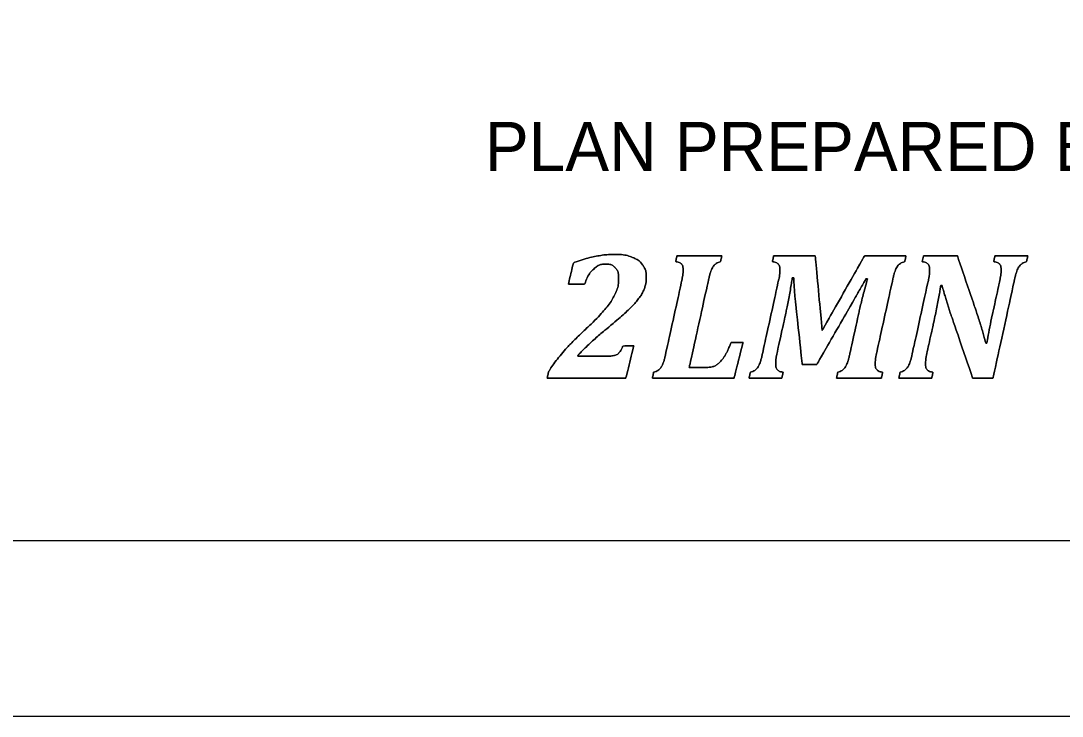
# Model space of a CAD drawing. Extents: x 0 to 36.9, y 0 to 22.
# Drawn here: x 2.291 to 5.257, y 0 to 1.981 of the extents above; entities that cross this region are included whole.
import ezdxf

# ---------------------------------------------------------------- set-up
doc = ezdxf.new("R2010")
doc.units = 0
for name, color, linetype in [('SH_Border', 7, 'Continuous'), ('SH_Cut_Line', 7, 'Continuous'), ('SH_Data', 7, 'Continuous'), ('SH_Text', 7, 'Continuous')]:
    doc.layers.add(name, color=color, linetype=linetype)

msp = doc.modelspace()

# ---------------------------------------------------------------- linework, layer by layer
at = {"layer": 'SH_Border'}
msp.add_lwpolyline([(1.5, 21.5), (33.5, 21.5), (33.5, 0.5), (1.5, 0.5)], close=True, dxfattribs=at)
at = {"layer": 'SH_Cut_Line'}
msp.add_lwpolyline([(0, 0), (34, 0), (34, 22), (0, 22)], close=True, dxfattribs=at)
at = {"layer": 'SH_Data'}
for points in [[(3.9615, 1.026), (3.9703, 1.026), (3.9771, 1.0266), (3.982, 1.0279), (3.9868, 1.0292), (3.9909, 1.0315), (3.9943, 1.035), (3.9977, 1.0385), (4.0014, 1.0451), (4.0055, 1.0548), (4.0055, 1.0548), (4.0365, 1.0548), (4.0365, 1.0548), (4.0365, 1.0548), (4.0139, 0.9635), (4.0139, 0.9635), (4.0139, 0.9635), (3.79, 0.9635), (3.79, 0.9635), (3.79, 0.9635), (3.7936, 0.9803), (3.7936, 0.9803), (3.8025, 0.9958), (3.8148, 1.0128), (3.8304, 1.0313), (3.846, 1.0499), (3.8678, 1.0725), (3.896, 1.0992), (3.9217, 1.1235), (3.9411, 1.1434), (3.954, 1.1588), (3.967, 1.1742), (3.9768, 1.189), (3.9835, 1.2033), (3.9902, 1.2176), (3.9935, 1.2324), (3.9935, 1.2477), (3.9935, 1.2601), (3.9903, 1.2699), (3.9839, 1.2771), (3.9774, 1.2844), (3.9688, 1.288), (3.958, 1.288), (3.9442, 1.288), (3.9324, 1.2833), (3.9224, 1.274), (3.9124, 1.2646), (3.9038, 1.2502), (3.8965, 1.2308), (3.8965, 1.2308), (3.8502, 1.2308), (3.8502, 1.2308), (3.8502, 1.2308), (3.8647, 1.2921), (3.8647, 1.2921), (3.8903, 1.3009), (3.9118, 1.307), (3.9294, 1.3104), (3.9469, 1.3138), (3.9645, 1.3155), (3.9821, 1.3155), (4.0024, 1.3155), (4.0194, 1.3127), (4.033, 1.307), (4.0467, 1.3013), (4.0566, 1.2936), (4.0629, 1.2839), (4.0692, 1.2742), (4.0723, 1.2632), (4.0723, 1.251), (4.0723, 1.2396), (4.0704, 1.2288), (4.0667, 1.2187), (4.063, 1.2086), (4.0568, 1.1981), (4.0483, 1.1871), (4.0397, 1.1761), (4.0281, 1.1639), (4.0135, 1.1503), (3.9988, 1.1368), (3.9784, 1.1193), (3.9521, 1.0977), (3.9397, 1.0875), (3.9264, 1.0757), (3.9121, 1.0625), (3.8978, 1.0492), (3.8864, 1.0379), (3.8779, 1.0285), (3.8779, 1.0285), (3.8774, 1.026), (3.8774, 1.026), (3.8774, 1.026), (3.9615, 1.026), (3.9615, 1.026)], [(3.9615, 1.026), (3.9615, 1.026), (3.8774, 1.026), (3.8774, 1.026), (3.8774, 1.026), (3.8779, 1.0285), (3.8779, 1.0285), (3.8864, 1.0379), (3.8978, 1.0492), (3.9121, 1.0625), (3.9264, 1.0757), (3.9397, 1.0875), (3.9521, 1.0977), (3.9784, 1.1193), (3.9988, 1.1368), (4.0135, 1.1503), (4.0281, 1.1639), (4.0397, 1.1761), (4.0483, 1.1871), (4.0568, 1.1981), (4.063, 1.2086), (4.0667, 1.2187), (4.0704, 1.2288), (4.0723, 1.2396), (4.0723, 1.251), (4.0723, 1.2632), (4.0692, 1.2742), (4.0629, 1.2839), (4.0566, 1.2936), (4.0467, 1.3013), (4.033, 1.307), (4.0194, 1.3127), (4.0024, 1.3155), (3.9821, 1.3155), (3.9645, 1.3155), (3.9469, 1.3138), (3.9294, 1.3104), (3.9118, 1.307), (3.8903, 1.3009), (3.8647, 1.2921), (3.8647, 1.2921), (3.8502, 1.2308), (3.8502, 1.2308), (3.8502, 1.2308), (3.8965, 1.2308), (3.8965, 1.2308), (3.9038, 1.2502), (3.9124, 1.2646), (3.9224, 1.274), (3.9324, 1.2833), (3.9442, 1.288), (3.958, 1.288), (3.9688, 1.288), (3.9774, 1.2844), (3.9839, 1.2771), (3.9903, 1.2699), (3.9935, 1.2601), (3.9935, 1.2477), (3.9935, 1.2324), (3.9902, 1.2176), (3.9835, 1.2033), (3.9768, 1.189), (3.967, 1.1742), (3.954, 1.1588), (3.9411, 1.1434), (3.9217, 1.1235), (3.896, 1.0992), (3.8678, 1.0725), (3.846, 1.0499), (3.8304, 1.0313), (3.8148, 1.0128), (3.8025, 0.9958), (3.7936, 0.9803), (3.7936, 0.9803), (3.79, 0.9635), (3.79, 0.9635), (3.79, 0.9635), (4.0139, 0.9635), (4.0139, 0.9635), (4.0139, 0.9635), (4.0365, 1.0548), (4.0365, 1.0548), (4.0365, 1.0548), (4.0055, 1.0548), (4.0055, 1.0548), (4.0014, 1.0451), (3.9977, 1.0385), (3.9943, 1.035), (3.9909, 1.0315), (3.9868, 1.0292), (3.982, 1.0279), (3.9771, 1.0266), (3.9703, 1.026), (3.9615, 1.026)], [(4.2425, 0.9938), (4.2508, 0.9938), (4.2573, 0.9945), (4.2618, 0.9959), (4.2664, 0.9972), (4.2706, 0.9994), (4.2743, 1.0022), (4.278, 1.0051), (4.2821, 1.0091), (4.2866, 1.0142), (4.2911, 1.0193), (4.2955, 1.026), (4.3, 1.0341), (4.3044, 1.0423), (4.3088, 1.0525), (4.3134, 1.0648), (4.3134, 1.0648), (4.348, 1.0648), (4.348, 1.0648), (4.348, 1.0648), (4.3221, 0.9635), (4.3221, 0.9635), (4.3221, 0.9635), (4.0896, 0.9635), (4.0896, 0.9635), (4.0896, 0.9635), (4.0931, 0.9803), (4.0931, 0.9803), (4.1002, 0.9823), (4.1057, 0.9852), (4.1095, 0.9887), (4.1133, 0.9923), (4.1166, 0.9974), (4.1193, 1.0039), (4.122, 1.0104), (4.1247, 1.0199), (4.1274, 1.0324), (4.1274, 1.0324), (4.1737, 1.2428), (4.1737, 1.2428), (4.1759, 1.2529), (4.177, 1.2628), (4.177, 1.2727), (4.177, 1.2798), (4.1753, 1.2851), (4.172, 1.2884), (4.1687, 1.2917), (4.1633, 1.2939), (4.1559, 1.2949), (4.1559, 1.2949), (4.1594, 1.3117), (4.1594, 1.3117), (4.1594, 1.3117), (4.2872, 1.3117), (4.2872, 1.3117), (4.2872, 1.3117), (4.2837, 1.2949), (4.2837, 1.2949), (4.2766, 1.2928), (4.2711, 1.29), (4.2673, 1.2865), (4.2635, 1.2829), (4.2602, 1.2778), (4.2575, 1.2713), (4.2548, 1.2647), (4.2521, 1.2552), (4.2494, 1.2428), (4.2494, 1.2428), (4.1945, 0.9938), (4.1945, 0.9938), (4.1945, 0.9938), (4.2425, 0.9938), (4.2425, 0.9938)], [(4.2425, 0.9938), (4.2425, 0.9938), (4.1945, 0.9938), (4.1945, 0.9938), (4.1945, 0.9938), (4.2494, 1.2428), (4.2494, 1.2428), (4.2521, 1.2552), (4.2548, 1.2647), (4.2575, 1.2713), (4.2602, 1.2778), (4.2635, 1.2829), (4.2673, 1.2865), (4.2711, 1.29), (4.2766, 1.2928), (4.2837, 1.2949), (4.2837, 1.2949), (4.2872, 1.3117), (4.2872, 1.3117), (4.2872, 1.3117), (4.1594, 1.3117), (4.1594, 1.3117), (4.1594, 1.3117), (4.1559, 1.2949), (4.1559, 1.2949), (4.1633, 1.2939), (4.1687, 1.2917), (4.172, 1.2884), (4.1753, 1.2851), (4.177, 1.2798), (4.177, 1.2727), (4.177, 1.2628), (4.1759, 1.2529), (4.1737, 1.2428), (4.1737, 1.2428), (4.1274, 1.0324), (4.1274, 1.0324), (4.1247, 1.0199), (4.122, 1.0104), (4.1193, 1.0039), (4.1166, 0.9974), (4.1133, 0.9923), (4.1095, 0.9887), (4.1057, 0.9852), (4.1002, 0.9823), (4.0931, 0.9803), (4.0931, 0.9803), (4.0896, 0.9635), (4.0896, 0.9635), (4.0896, 0.9635), (4.3221, 0.9635), (4.3221, 0.9635), (4.3221, 0.9635), (4.348, 1.0648), (4.348, 1.0648), (4.348, 1.0648), (4.3134, 1.0648), (4.3134, 1.0648), (4.3088, 1.0525), (4.3044, 1.0423), (4.3, 1.0341), (4.2955, 1.026), (4.2911, 1.0193), (4.2866, 1.0142), (4.2821, 1.0091), (4.278, 1.0051), (4.2743, 1.0022), (4.2706, 0.9994), (4.2664, 0.9972), (4.2618, 0.9959), (4.2573, 0.9945), (4.2508, 0.9938), (4.2425, 0.9938)], [(4.5533, 1.3117), (4.5533, 1.3117), (4.5731, 1.0987), (4.5731, 1.0987), (4.5731, 1.0987), (4.6935, 1.3117), (4.6935, 1.3117), (4.6935, 1.3117), (4.8117, 1.3117), (4.8117, 1.3117), (4.8117, 1.3117), (4.8081, 1.2949), (4.8081, 1.2949), (4.801, 1.2928), (4.7955, 1.29), (4.7917, 1.2865), (4.7879, 1.2829), (4.7846, 1.2778), (4.7819, 1.2713), (4.7792, 1.2647), (4.7765, 1.2552), (4.7738, 1.2428), (4.7738, 1.2428), (4.7276, 1.0324), (4.7276, 1.0324), (4.7265, 1.0279), (4.7259, 1.0244), (4.7255, 1.0219), (4.7252, 1.0193), (4.7249, 1.0166), (4.7246, 1.0136), (4.7244, 1.0106), (4.7243, 1.0069), (4.7243, 1.0025), (4.7243, 0.9954), (4.7259, 0.9901), (4.7292, 0.9868), (4.7325, 0.9835), (4.7379, 0.9813), (4.7453, 0.9803), (4.7453, 0.9803), (4.7418, 0.9635), (4.7418, 0.9635), (4.7418, 0.9635), (4.614, 0.9635), (4.614, 0.9635), (4.614, 0.9635), (4.6175, 0.9803), (4.6175, 0.9803), (4.6247, 0.9823), (4.6301, 0.9852), (4.6339, 0.9887), (4.6377, 0.9923), (4.641, 0.9974), (4.6437, 1.0039), (4.6464, 1.0104), (4.6491, 1.0199), (4.6518, 1.0324), (4.6518, 1.0324), (4.6752, 1.1395), (4.6752, 1.1395), (4.6778, 1.1511), (4.6814, 1.1665), (4.6861, 1.1858), (4.6909, 1.2051), (4.6964, 1.2253), (4.7027, 1.2464), (4.7027, 1.2464), (4.6976, 1.2464), (4.6976, 1.2464), (4.6896, 1.2318), (4.6811, 1.2165), (4.6719, 1.2007), (4.6719, 1.2007), (4.5576, 1.002), (4.5576, 1.002), (4.5576, 1.002), (4.5164, 1.002), (4.5164, 1.002), (4.5164, 1.002), (4.4997, 1.1553), (4.4997, 1.1553), (4.4975, 1.1747), (4.4958, 1.1916), (4.4947, 1.2061), (4.4936, 1.2205), (4.4927, 1.2348), (4.492, 1.249), (4.492, 1.249), (4.488, 1.249), (4.488, 1.249), (4.4856, 1.2333), (4.4825, 1.2154), (4.4788, 1.1952), (4.4751, 1.1751), (4.4717, 1.1581), (4.4687, 1.1444), (4.4687, 1.1444), (4.444, 1.0324), (4.444, 1.0324), (4.443, 1.0279), (4.4423, 1.0244), (4.442, 1.0219), (4.4416, 1.0193), (4.4413, 1.0166), (4.4411, 1.0136), (4.4408, 1.0106), (4.4407, 1.0069), (4.4407, 1.0025), (4.4407, 0.9954), (4.4424, 0.9901), (4.4457, 0.9868), (4.449, 0.9835), (4.4543, 0.9813), (4.4618, 0.9803), (4.4618, 0.9803), (4.4582, 0.9635), (4.4582, 0.9635), (4.4582, 0.9635), (4.365, 0.9635), (4.365, 0.9635), (4.365, 0.9635), (4.3686, 0.9803), (4.3686, 0.9803), (4.3757, 0.9823), (4.3811, 0.9852), (4.3849, 0.9887), (4.3888, 0.9923), (4.392, 0.9974), (4.3947, 1.0039), (4.3974, 1.0104), (4.4001, 1.0199), (4.4029, 1.0324), (4.4029, 1.0324), (4.4491, 1.2428), (4.4491, 1.2428), (4.4513, 1.2529), (4.4524, 1.2628), (4.4524, 1.2727), (4.4524, 1.2798), (4.4507, 1.2851), (4.4474, 1.2884), (4.4441, 1.2917), (4.4388, 1.2939), (4.4313, 1.2949), (4.4313, 1.2949), (4.4349, 1.3117), (4.4349, 1.3117), (4.4349, 1.3117), (4.5533, 1.3117), (4.5533, 1.3117)], [(4.5533, 1.3117), (4.5533, 1.3117), (4.4349, 1.3117), (4.4349, 1.3117), (4.4349, 1.3117), (4.4313, 1.2949), (4.4313, 1.2949), (4.4388, 1.2939), (4.4441, 1.2917), (4.4474, 1.2884), (4.4507, 1.2851), (4.4524, 1.2798), (4.4524, 1.2727), (4.4524, 1.2628), (4.4513, 1.2529), (4.4491, 1.2428), (4.4491, 1.2428), (4.4029, 1.0324), (4.4029, 1.0324), (4.4001, 1.0199), (4.3974, 1.0104), (4.3947, 1.0039), (4.392, 0.9974), (4.3888, 0.9923), (4.3849, 0.9887), (4.3811, 0.9852), (4.3757, 0.9823), (4.3686, 0.9803), (4.3686, 0.9803), (4.365, 0.9635), (4.365, 0.9635), (4.365, 0.9635), (4.4582, 0.9635), (4.4582, 0.9635), (4.4582, 0.9635), (4.4618, 0.9803), (4.4618, 0.9803), (4.4543, 0.9813), (4.449, 0.9835), (4.4457, 0.9868), (4.4424, 0.9901), (4.4407, 0.9954), (4.4407, 1.0025), (4.4407, 1.0069), (4.4408, 1.0106), (4.4411, 1.0136), (4.4413, 1.0166), (4.4416, 1.0193), (4.442, 1.0219), (4.4423, 1.0244), (4.443, 1.0279), (4.444, 1.0324), (4.444, 1.0324), (4.4687, 1.1444), (4.4687, 1.1444), (4.4717, 1.1581), (4.4751, 1.1751), (4.4788, 1.1952), (4.4825, 1.2154), (4.4856, 1.2333), (4.488, 1.249), (4.488, 1.249), (4.492, 1.249), (4.492, 1.249), (4.4927, 1.2348), (4.4936, 1.2205), (4.4947, 1.2061), (4.4958, 1.1916), (4.4975, 1.1747), (4.4997, 1.1553), (4.4997, 1.1553), (4.5164, 1.002), (4.5164, 1.002), (4.5164, 1.002), (4.5576, 1.002), (4.5576, 1.002), (4.5576, 1.002), (4.6719, 1.2007), (4.6719, 1.2007), (4.6811, 1.2165), (4.6896, 1.2318), (4.6976, 1.2464), (4.6976, 1.2464), (4.7027, 1.2464), (4.7027, 1.2464), (4.6964, 1.2253), (4.6909, 1.2051), (4.6861, 1.1858), (4.6814, 1.1665), (4.6778, 1.1511), (4.6752, 1.1395), (4.6752, 1.1395), (4.6518, 1.0324), (4.6518, 1.0324), (4.6491, 1.0199), (4.6464, 1.0104), (4.6437, 1.0039), (4.641, 0.9974), (4.6377, 0.9923), (4.6339, 0.9887), (4.6301, 0.9852), (4.6247, 0.9823), (4.6175, 0.9803), (4.6175, 0.9803), (4.614, 0.9635), (4.614, 0.9635), (4.614, 0.9635), (4.7418, 0.9635), (4.7418, 0.9635), (4.7418, 0.9635), (4.7453, 0.9803), (4.7453, 0.9803), (4.7379, 0.9813), (4.7325, 0.9835), (4.7292, 0.9868), (4.7259, 0.9901), (4.7243, 0.9954), (4.7243, 1.0025), (4.7243, 1.0069), (4.7244, 1.0106), (4.7246, 1.0136), (4.7249, 1.0166), (4.7252, 1.0193), (4.7255, 1.0219), (4.7259, 1.0244), (4.7265, 1.0279), (4.7276, 1.0324), (4.7276, 1.0324), (4.7738, 1.2428), (4.7738, 1.2428), (4.7765, 1.2552), (4.7792, 1.2647), (4.7819, 1.2713), (4.7846, 1.2778), (4.7879, 1.2829), (4.7917, 1.2865), (4.7955, 1.29), (4.801, 1.2928), (4.8081, 1.2949), (4.8081, 1.2949), (4.8117, 1.3117), (4.8117, 1.3117), (4.8117, 1.3117), (4.6935, 1.3117), (4.6935, 1.3117), (4.6935, 1.3117), (4.5731, 1.0987), (4.5731, 1.0987), (4.5731, 1.0987), (4.5533, 1.3117), (4.5533, 1.3117)], [(4.8615, 1.3117), (4.8615, 1.3117), (4.958, 1.3117), (4.958, 1.3117), (4.958, 1.3117), (5.007, 1.1673), (5.007, 1.1673), (5.0204, 1.128), (5.031, 1.0933), (5.0388, 1.0632), (5.0388, 1.0632), (5.0421, 1.0632), (5.0421, 1.0632), (5.047, 1.0926), (5.0535, 1.1252), (5.0614, 1.1609), (5.0614, 1.1609), (5.0792, 1.2428), (5.0792, 1.2428), (5.0814, 1.253), (5.0825, 1.263), (5.0825, 1.2727), (5.0825, 1.2798), (5.0809, 1.2851), (5.0776, 1.2884), (5.0743, 1.2917), (5.0689, 1.2939), (5.0614, 1.2949), (5.0614, 1.2949), (5.065, 1.3117), (5.065, 1.3117), (5.065, 1.3117), (5.1585, 1.3117), (5.1585, 1.3117), (5.1585, 1.3117), (5.1549, 1.2949), (5.1549, 1.2949), (5.1478, 1.2928), (5.1423, 1.29), (5.1385, 1.2865), (5.1347, 1.2829), (5.1315, 1.2778), (5.1288, 1.2713), (5.126, 1.2647), (5.1233, 1.2552), (5.1206, 1.2428), (5.1206, 1.2428), (5.0594, 0.9635), (5.0594, 0.9635), (5.0594, 0.9635), (5.0015, 0.9635), (5.0015, 0.9635), (5.0015, 0.9635), (4.9405, 1.1418), (4.9405, 1.1418), (4.9357, 1.1557), (4.9315, 1.1688), (4.9278, 1.181), (4.924, 1.1931), (4.9196, 1.2086), (4.9143, 1.2273), (4.9143, 1.2273), (4.9105, 1.2275), (4.9105, 1.2275), (4.9091, 1.2161), (4.9066, 1.2004), (4.9027, 1.1805), (4.8989, 1.1605), (4.8944, 1.1388), (4.8892, 1.1155), (4.8892, 1.1155), (4.8709, 1.0324), (4.8709, 1.0324), (4.8698, 1.0279), (4.8692, 1.0244), (4.8688, 1.0219), (4.8685, 1.0193), (4.8682, 1.0166), (4.8679, 1.0136), (4.8677, 1.0106), (4.8676, 1.0069), (4.8676, 1.0025), (4.8676, 0.9954), (4.8692, 0.9901), (4.8725, 0.9868), (4.8758, 0.9835), (4.8812, 0.9813), (4.8886, 0.9803), (4.8886, 0.9803), (4.8851, 0.9635), (4.8851, 0.9635), (4.8851, 0.9635), (4.7916, 0.9635), (4.7916, 0.9635), (4.7916, 0.9635), (4.7951, 0.9803), (4.7951, 0.9803), (4.8023, 0.9823), (4.8077, 0.9852), (4.8115, 0.9887), (4.8153, 0.9923), (4.8186, 0.9974), (4.8213, 1.0039), (4.824, 1.0104), (4.8267, 1.0199), (4.8294, 1.0324), (4.8294, 1.0324), (4.8757, 1.2428), (4.8757, 1.2428), (4.8779, 1.2529), (4.879, 1.2628), (4.879, 1.2727), (4.879, 1.2798), (4.8773, 1.2851), (4.874, 1.2884), (4.8707, 1.2917), (4.8654, 1.2939), (4.8579, 1.2949), (4.8579, 1.2949), (4.8615, 1.3117), (4.8615, 1.3117)], [(4.8615, 1.3117), (4.8615, 1.3117), (4.8579, 1.2949), (4.8579, 1.2949), (4.8654, 1.2939), (4.8707, 1.2917), (4.874, 1.2884), (4.8773, 1.2851), (4.879, 1.2798), (4.879, 1.2727), (4.879, 1.2628), (4.8779, 1.2529), (4.8757, 1.2428), (4.8757, 1.2428), (4.8294, 1.0324), (4.8294, 1.0324), (4.8267, 1.0199), (4.824, 1.0104), (4.8213, 1.0039), (4.8186, 0.9974), (4.8153, 0.9923), (4.8115, 0.9887), (4.8077, 0.9852), (4.8023, 0.9823), (4.7951, 0.9803), (4.7951, 0.9803), (4.7916, 0.9635), (4.7916, 0.9635), (4.7916, 0.9635), (4.8851, 0.9635), (4.8851, 0.9635), (4.8851, 0.9635), (4.8886, 0.9803), (4.8886, 0.9803), (4.8812, 0.9813), (4.8758, 0.9835), (4.8725, 0.9868), (4.8692, 0.9901), (4.8676, 0.9954), (4.8676, 1.0025), (4.8676, 1.0069), (4.8677, 1.0106), (4.8679, 1.0136), (4.8682, 1.0166), (4.8685, 1.0193), (4.8688, 1.0219), (4.8692, 1.0244), (4.8698, 1.0279), (4.8709, 1.0324), (4.8709, 1.0324), (4.8892, 1.1155), (4.8892, 1.1155), (4.8944, 1.1388), (4.8989, 1.1605), (4.9027, 1.1805), (4.9066, 1.2004), (4.9091, 1.2161), (4.9105, 1.2275), (4.9105, 1.2275), (4.9143, 1.2273), (4.9143, 1.2273), (4.9196, 1.2086), (4.924, 1.1931), (4.9278, 1.181), (4.9315, 1.1688), (4.9357, 1.1557), (4.9405, 1.1418), (4.9405, 1.1418), (5.0015, 0.9635), (5.0015, 0.9635), (5.0015, 0.9635), (5.0594, 0.9635), (5.0594, 0.9635), (5.0594, 0.9635), (5.1206, 1.2428), (5.1206, 1.2428), (5.1233, 1.2552), (5.126, 1.2647), (5.1288, 1.2713), (5.1315, 1.2778), (5.1347, 1.2829), (5.1385, 1.2865), (5.1423, 1.29), (5.1478, 1.2928), (5.1549, 1.2949), (5.1549, 1.2949), (5.1585, 1.3117), (5.1585, 1.3117), (5.1585, 1.3117), (5.065, 1.3117), (5.065, 1.3117), (5.065, 1.3117), (5.0614, 1.2949), (5.0614, 1.2949), (5.0689, 1.2939), (5.0743, 1.2917), (5.0776, 1.2884), (5.0809, 1.2851), (5.0825, 1.2798), (5.0825, 1.2727), (5.0825, 1.263), (5.0814, 1.253), (5.0792, 1.2428), (5.0792, 1.2428), (5.0614, 1.1609), (5.0614, 1.1609), (5.0535, 1.1252), (5.047, 1.0926), (5.0421, 1.0632), (5.0421, 1.0632), (5.0388, 1.0632), (5.0388, 1.0632), (5.031, 1.0933), (5.0204, 1.128), (5.007, 1.1673), (5.007, 1.1673), (4.958, 1.3117), (4.958, 1.3117), (4.958, 1.3117), (4.8615, 1.3117), (4.8615, 1.3117)]]:
    msp.add_open_spline(points, degree=3, dxfattribs=at)

# ---------------------------------------------------------------- texts
at = {"layer": 'SH_Text'}
msp.add_text('PLAN PREPARED BY:', height=0.14, dxfattribs=at).set_placement((3.6125, 1.553))

doc.saveas('drawing.dxf')
